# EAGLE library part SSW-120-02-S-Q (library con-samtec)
THROUGH-HOLE .025" SQ POST SOCKET Source: Samtec SSW.pdf
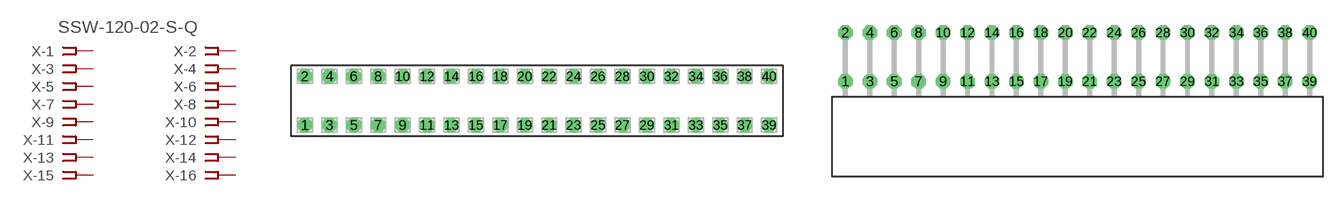
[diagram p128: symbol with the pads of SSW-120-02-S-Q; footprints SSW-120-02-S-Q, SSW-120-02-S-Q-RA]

Designator prefix X; gates -1=FPINV -2=FPIN -3=FPIN -4=FPIN -5=FPIN -6=FPIN -7=FPIN -8=FPIN -9=FPIN -10=FPIN -11=FPIN -12=FPIN -13=FPIN -14=FPIN -15=FPIN -16=FPIN -17=FPIN -18=FPIN -19=FPIN -20=FPIN -21=FPIN -22=FPIN -23=FPIN -24=FPIN -25=FPIN -26=FPIN -27=FPIN -28=FPIN -29=FPIN -30=FPIN -31=FPIN -32=FPIN -33=FPIN -34=FPIN -35=FPIN -36=FPIN -37=FPIN -38=FPIN -39=FPIN -40=FPIN

## SSW-120-02-S-Q (MPN: SSW-120-02-S-Q; OC_FARNELL: unknown; OC_NEWARK: 82P8256)  [SSW-120-02-S-Q]
1  -1:1  pas
2  -2:1  pas
3  -3:1  pas
4  -4:1  pas
5  -5:1  pas
6  -6:1  pas
7  -7:1  pas
8  -8:1  pas
9  -9:1  pas
10  -10:1  pas
11  -11:1  pas
12  -12:1  pas
13  -13:1  pas
14  -14:1  pas
15  -15:1  pas
16  -16:1  pas
17  -17:1  pas
18  -18:1  pas
19  -19:1  pas
20  -20:1  pas
21  -21:1  pas
22  -22:1  pas
23  -23:1  pas
24  -24:1  pas
25  -25:1  pas
26  -26:1  pas
27  -27:1  pas
28  -28:1  pas
29  -29:1  pas
30  -30:1  pas
31  -31:1  pas
32  -32:1  pas
33  -33:1  pas
34  -34:1  pas
35  -35:1  pas
36  -36:1  pas
37  -37:1  pas
38  -38:1  pas
39  -39:1  pas
40  -40:1  pas

## SSW-120-02-S-QRA (MPN: SSW-120-02-S-Q-RA; OC_FARNELL: unknown; OC_NEWARK: 82P8257)  [SSW-120-02-S-Q-RA]
Pads as for SSW-120-02-S-Q

## Footprint SSW-120-02-S-Q (pad centres in mm)
THROUGH-HOLE .025" SQ POST SOCKET Source: Samtec SSW.pdf
drill 1 pad 1.5 octagon: 1 -24.13,-2.54; 2 -24.13,2.54; 3 -21.59,-2.54; 4 -21.59,2.54; 5 -19.05,-2.54; 6 -19.05,2.54; 7 -16.51,-2.54; 8 -16.51,2.54; 9 -13.97,-2.54; 10 -13.97,2.54; 11 -11.43,-2.54; 12 -11.43,2.54; 13 -8.89,-2.54; 14 -8.89,2.54; 15 -6.35,-2.54; 16 -6.35,2.54; 17 -3.81,-2.54; 18 -3.81,2.54; 19 -1.27,-2.54; 20 -1.27,2.54; 21 1.27,-2.54; 22 1.27,2.54; 23 3.81,-2.54; 24 3.81,2.54; 25 6.35,-2.54; 26 6.35,2.54; 27 8.89,-2.54; 28 8.89,2.54; 29 11.43,-2.54; 30 11.43,2.54; 31 13.97,-2.54; 32 13.97,2.54; 33 16.51,-2.54; 34 16.51,2.54; 35 19.05,-2.54; 36 19.05,2.54; 37 21.59,-2.54; 38 21.59,2.54; 39 24.13,-2.54; 40 24.13,2.54

## Footprint SSW-120-02-S-Q-RA (pad centres in mm)
THROUGH-HOLE .025" SQ POST SOCKET Source: Samtec SSW.pdf
drill 1 pad 1.5 octagon: 1 -24.13,1.524; 2 -24.13,6.604; 3 -21.59,1.524; 4 -21.59,6.604; 5 -19.05,1.524; 6 -19.05,6.604; 7 -16.51,1.524; 8 -16.51,6.604; 9 -13.97,1.524; 10 -13.97,6.604; 11 -11.43,1.524; 12 -11.43,6.604; 13 -8.89,1.524; 14 -8.89,6.604; 15 -6.35,1.524; 16 -6.35,6.604; 17 -3.81,1.524; 18 -3.81,6.604; 19 -1.27,1.524; 20 -1.27,6.604; 21 1.27,1.524; 22 1.27,6.604; 23 3.81,1.524; 24 3.81,6.604; 25 6.35,1.524; 26 6.35,6.604; 27 8.89,1.524; 28 8.89,6.604; 29 11.43,1.524; 30 11.43,6.604; 31 13.97,1.524; 32 13.97,6.604; 33 16.51,1.524; 34 16.51,6.604; 35 19.05,1.524; 36 19.05,6.604; 37 21.59,1.524; 38 21.59,6.604; 39 24.13,1.524; 40 24.13,6.604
